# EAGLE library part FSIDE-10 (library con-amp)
AMP connector
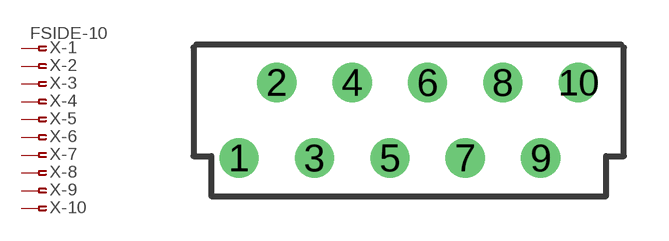
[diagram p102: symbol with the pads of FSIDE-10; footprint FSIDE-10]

Designator prefix X; gates -1=PIN-FV -2=PIN-F -3=PIN-F -4=PIN-F -5=PIN-F -6=PIN-F -7=PIN-F -8=PIN-F -9=PIN-F -10=PIN-F

## FSIDE-10 (OC_FARNELL: unknown; OC_NEWARK: unknown)  [FSIDE-10]
1  -1:1  pas
2  -2:1  pas
3  -3:1  pas
4  -4:1  pas
5  -5:1  pas
6  -6:1  pas
7  -7:1  pas
8  -8:1  pas
9  -9:1  pas
10  -10:1  pas

## Footprint FSIDE-10 (pad centres in mm)
AMP connector
drill 0.813 round: 1 -5.715,-1.27; 2 -4.445,1.27; 3 -3.175,-1.27; 4 -1.905,1.27; 5 -0.635,-1.27; 6 0.635,1.27; 7 1.905,-1.27; 8 3.175,1.27; 9 4.445,-1.27; 10 5.715,1.27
